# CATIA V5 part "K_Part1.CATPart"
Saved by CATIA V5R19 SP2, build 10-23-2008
Part number: Squelette_General
Publications: "Distance_Inter_Pivot", "Epaisseur_Cloison", "Epaisseur_Branche", "Epaisseur_LogementVérin", "Epaisseur_Vérin", "Centre_Pivot_Support1", "Centre_Pivot_Support2", "Plan_Réf_Support", "Pivot_Vérin_Branche1", "Centre_Pivot_LogementVérin", "Centre_Pivot_Branche2", "Point.7", "Plan_Branche2", "Plan_LogementVérin", "Plan.4", "Encombrement_Lame", "Plan.5", "Point.8", "Point.9", "Point.10", "Point.11", "Point.12", "Droite_DirectionGlissière", "Plan.6", "Plan_Capot1", "Plan.9"
Bounding box of the stored display mesh (mm): x -13.5 to 12.5, y 0 to 200, z -27 to 10
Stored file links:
  G:\Khaled_CFAO_2011\SIL\SIL_GR1\mneves\Khaled\CAD_CATIA_Modifie\K_Part1.CATPart
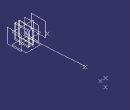
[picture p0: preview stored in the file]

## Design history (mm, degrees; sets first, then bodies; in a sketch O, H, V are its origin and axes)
Parameters
  Distance_Inter_Pivot = 200 mm
  Epaisseur_Cloison = 3 mm
  Epaisseur_Branche = 15 mm
  `Epaisseur_LogementVérin` = 10 mm
  `Epaisseur_Vérin` = 6 mm
  Encombrement_Lame = 12 mm
Set1
  Point1 "Centre_Pivot_Support1": (0, 0, 0)
  Point2 "Centre_Pivot_Support2": (0, 200 {= Distance_Inter_Pivot}, 0)
  Plane1 "Plan_Réf_Support": type Offset, RefPlane yz-plane, Offset 0
  Point3 "Pivot_Vérin_Branche1": (12.5 {= (`Epaisseur_LogementVérin` /2)+`Epaisseur_Vérin` +(Epaisseur_Cloison /2)}, 160 {= Distance_Inter_Pivot -(Distance_Inter_Pivot /5)}, 10 {= Distance_Inter_Pivot /20})
  Point4 "Centre_Pivot_LogementVérin": (1.5 {= Epaisseur_Cloison /2}, 0, 0)
  Point5 "Centre_Pivot_Branche2": (-13.5 {= -((Epaisseur_Cloison /2)+Encombrement_Lame )}, 0, 0)
  Point6 "Centre_Pivot_Branche1": (12.5 {= (`Epaisseur_LogementVérin` /2)+(Epaisseur_Cloison )/2+`Epaisseur_Vérin`}, 200 {= Distance_Inter_Pivot}, 0)
  Plane2 "Plan_Branche2": type Offset, RefPlane Plane1, Offset 13.5 {= (Epaisseur_Cloison /2)+Encombrement_Lame}, reversed
  Plane3 "Plan_LogementVérin": type Offset, RefPlane Plane1, Offset 1.5 {= Epaisseur_Cloison /2}
  Plane4 "Plan_Branche1": type Offset, RefPlane Plane1, Offset 12.5 {= (Epaisseur_Cloison/2)+(`Epaisseur_LogementVérin`/2)+`Epaisseur_Vérin`}
  Plane5: type Offset, RefPlane xy-plane, Offset 27 {= Distance_Inter_Pivot /8+Distance_Inter_Pivot /40-Epaisseur_Cloison}, reversed
  Point7: (-7.5 {= -((Epaisseur_Cloison /2)+Encombrement_Lame/2 )}, 7 {= Distance_Inter_Pivot /40+2mm}, -27 {= -(Distance_Inter_Pivot /8+Distance_Inter_Pivot /40-Epaisseur_Cloison )})
  Point8: (-7.5 {= -((Epaisseur_Cloison /2)+(Encombrement_Lame /2))}, 193 {= Distance_Inter_Pivot -Distance_Inter_Pivot /40+-2mm}, -27 {= -(Distance_Inter_Pivot /8+Distance_Inter_Pivot /40-Epaisseur_Cloison )})
  Point9: (-13.5 {= -((Epaisseur_Cloison )/2+Encombrement_Lame )}, 40 {= Distance_Inter_Pivot /5}, 10 {= Distance_Inter_Pivot /20})
  Plane6: type Offset, RefPlane Plane1, Offset 9.5 {= Epaisseur_Cloison /2+`Epaisseur_LogementVérin` /2+`Epaisseur_Vérin` /2}
  Point10: (9.5 {= Epaisseur_Cloison /2+`Epaisseur_LogementVérin` /2+`Epaisseur_Vérin` /2}, 0, 0)
  Point11: (9.5 {= Epaisseur_Cloison /2+`Epaisseur_LogementVérin` /2+`Epaisseur_Vérin` /2}, 160 {= Distance_Inter_Pivot -Distance_Inter_Pivot /5}, 10 {= Distance_Inter_Pivot /20})
  Line1 "Droite_DirectionGlissière": type PtPt, FirstPoint Point10, SecondPoint Point11
  Plane7 "Plan_Capot1": type Offset, RefPlane Plane1, Offset 30.5 {= Epaisseur_Cloison /2+Encombrement_Lame +Epaisseur_Branche +2mm}
  Plane8 "Plan_Capot2": type Offset, RefPlane Plane1, Offset 30.5 {= Epaisseur_Cloison /2+Encombrement_Lame +Epaisseur_Branche +2mm}, reversed
Body1 (main body)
